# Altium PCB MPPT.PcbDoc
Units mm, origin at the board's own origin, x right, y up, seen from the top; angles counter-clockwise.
Board outline 84 x 83.24 mm, 2 copper layers (Top Layer, Bottom Layer); 69 components, 41 nets, 225 pads, 101 vias.
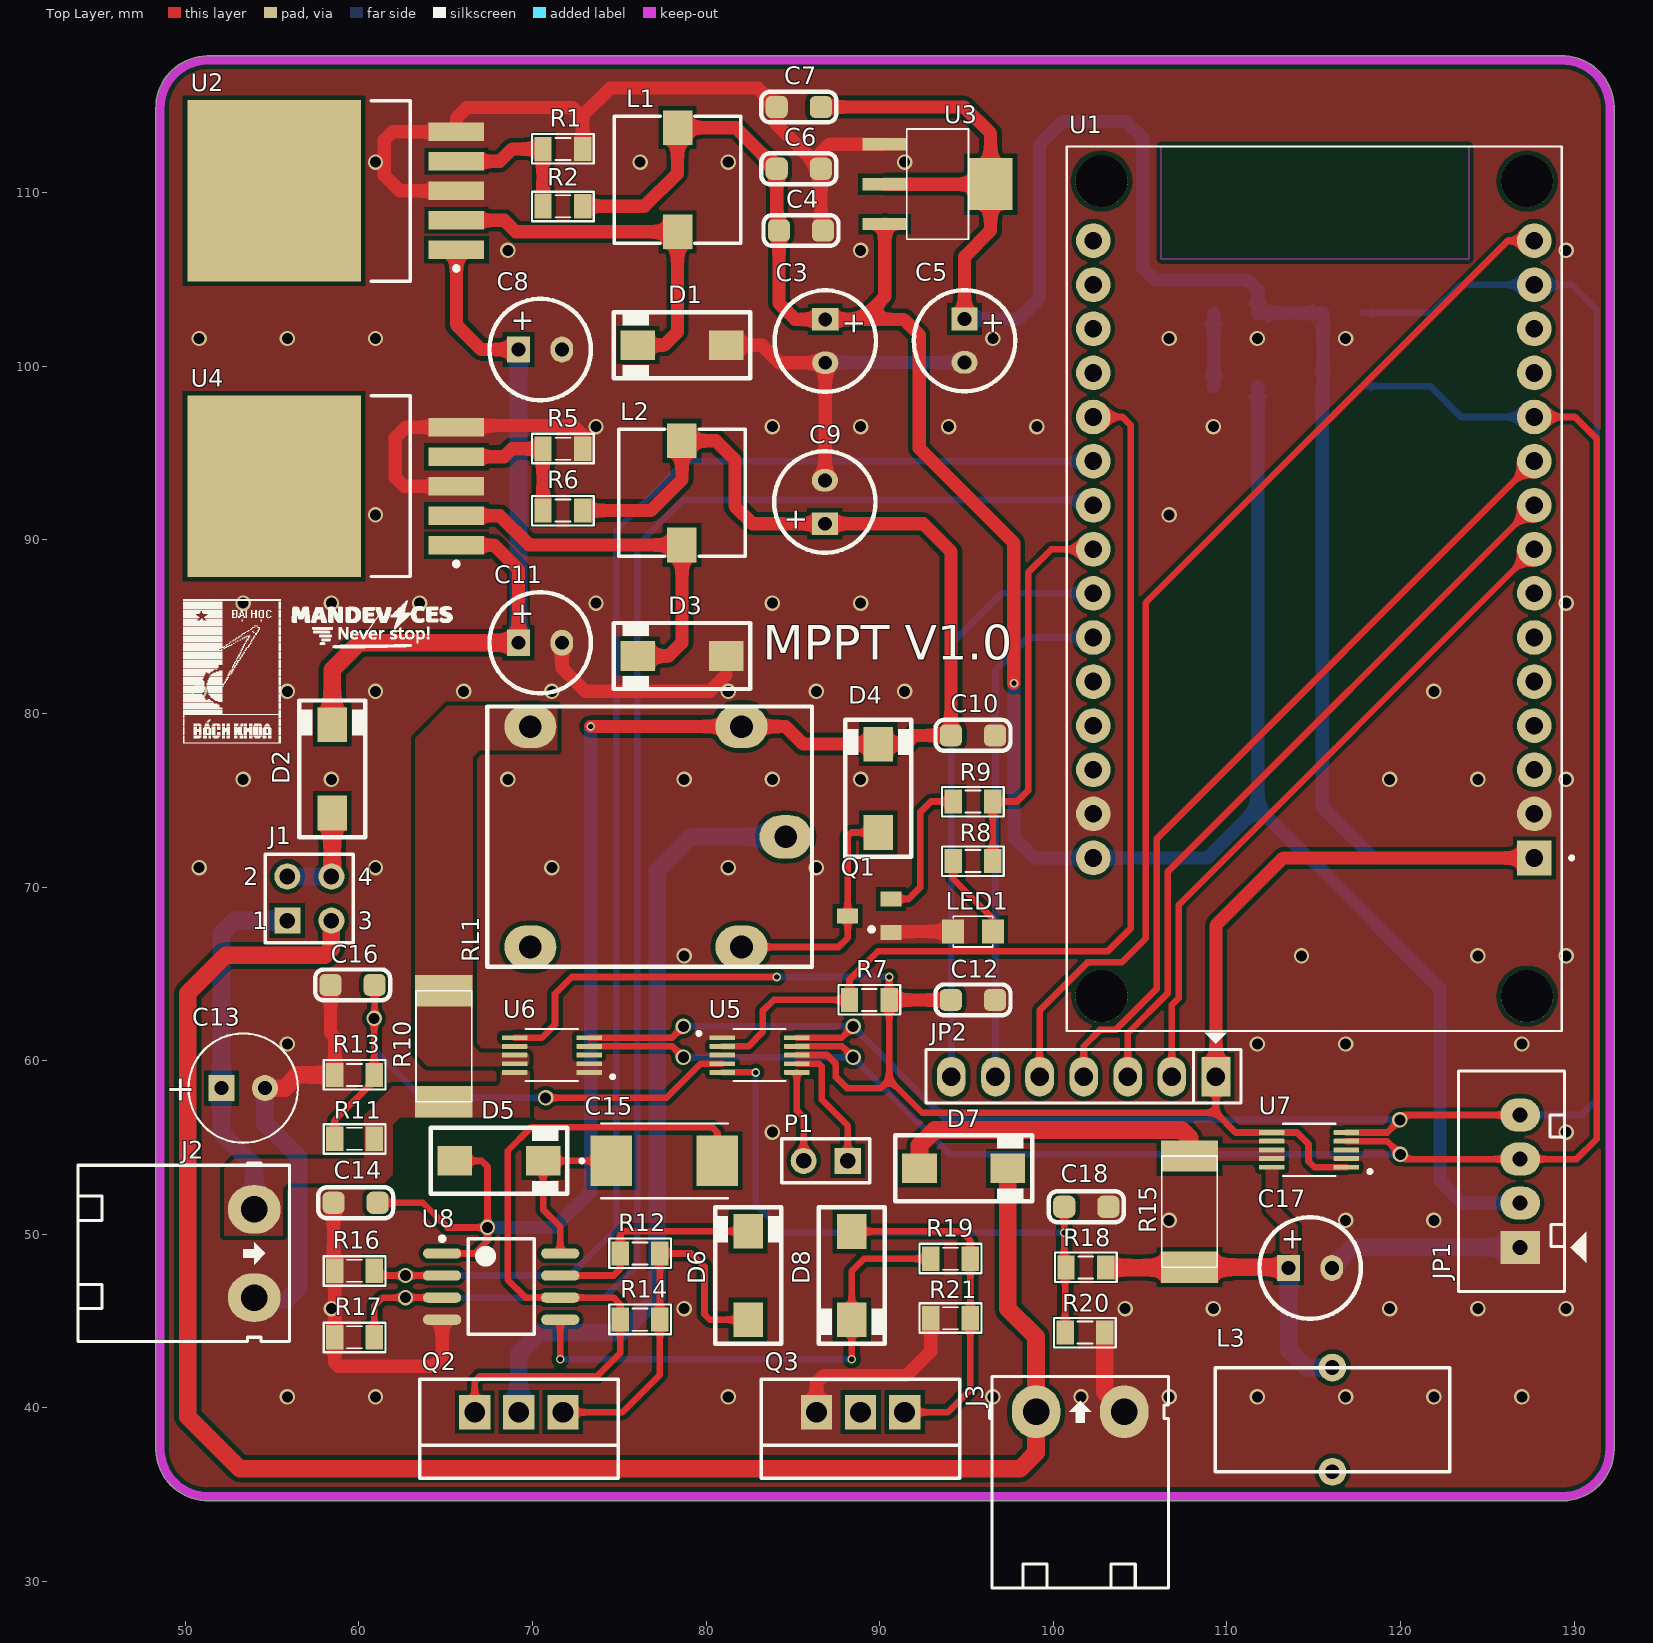
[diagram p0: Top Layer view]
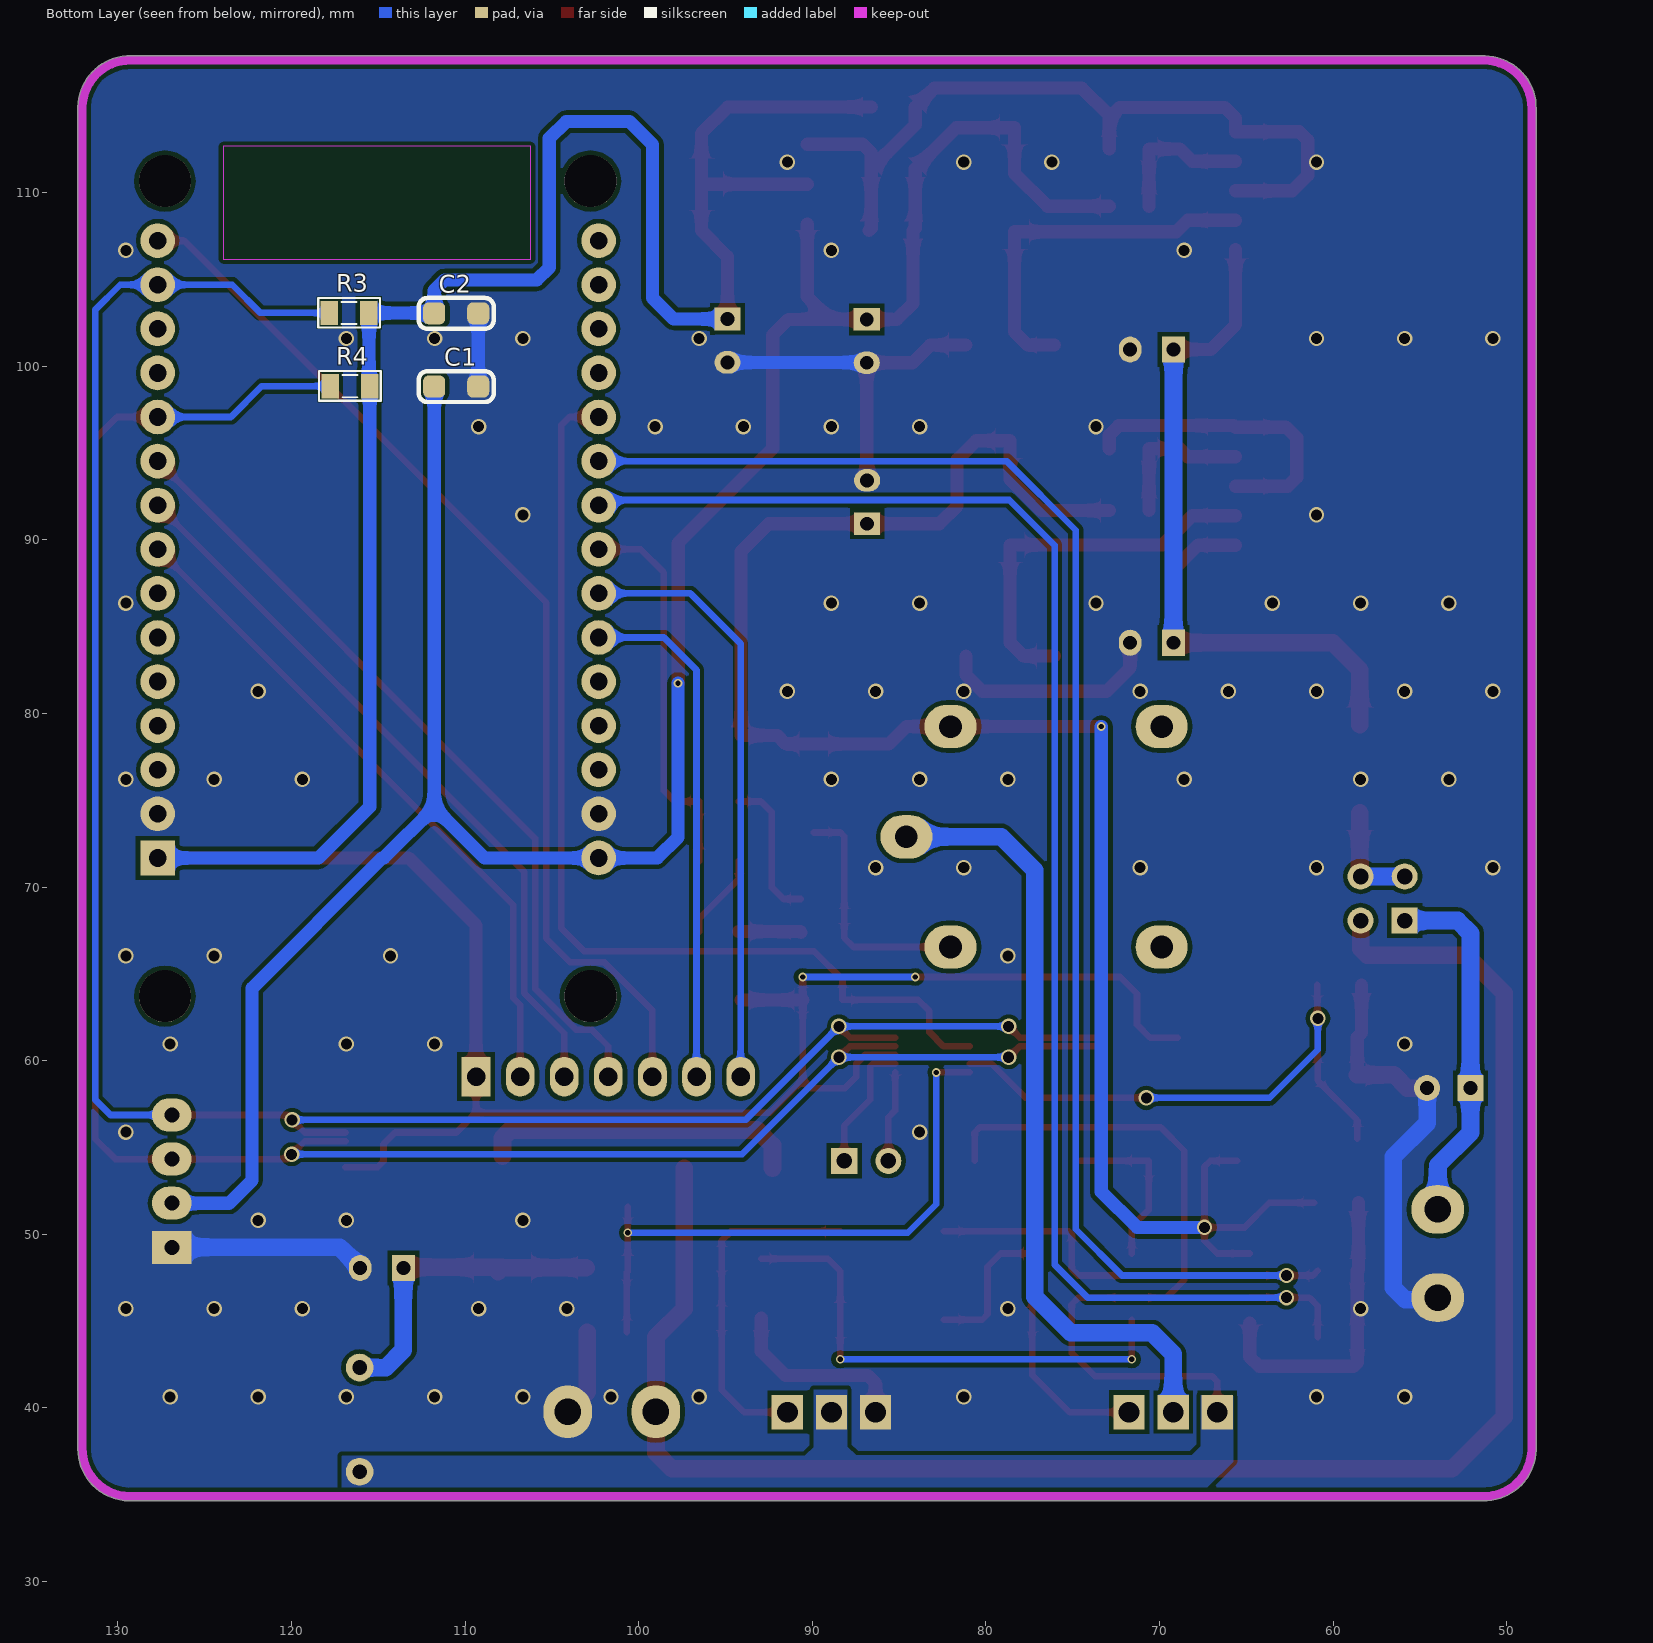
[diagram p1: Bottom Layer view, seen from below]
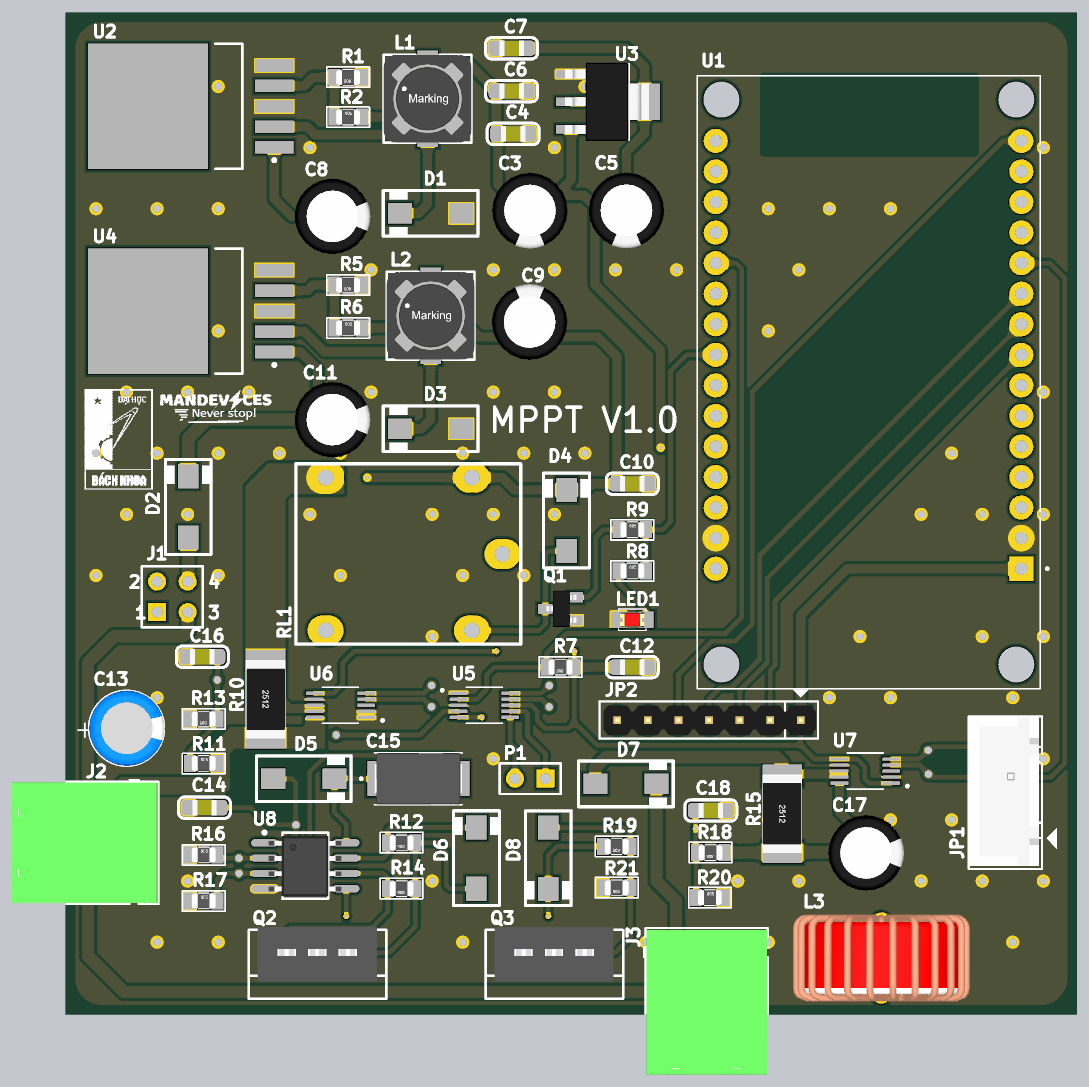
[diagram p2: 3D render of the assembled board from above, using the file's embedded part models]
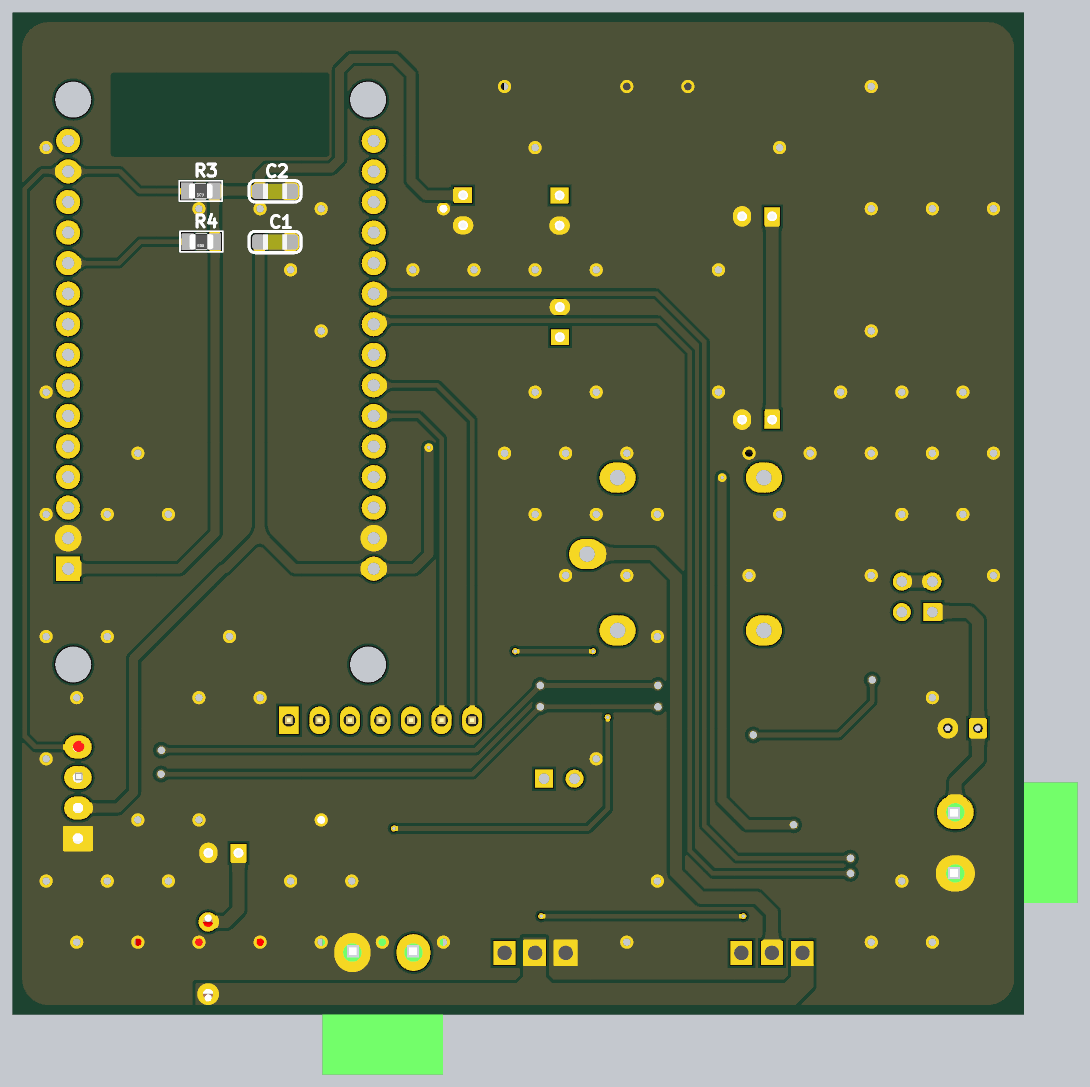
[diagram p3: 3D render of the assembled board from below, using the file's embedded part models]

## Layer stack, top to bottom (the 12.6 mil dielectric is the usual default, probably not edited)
Top Solder: solder mask 0.0102, Solder Resist, Dk 3.5
Top Layer: signal copper 0.0356
Dielectric 1: dielectric 0.32, FR-4, Dk 4.8
Bottom Layer: signal copper 0.0356
Bottom Solder: solder mask 0.0102, Solder Resist, Dk 3.5

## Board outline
48.31,37.587 cw(c48.565,37.592) 48.312,37.624 48.312,114.805 cw(c48.565,114.832) 48.311,114.828 cw(c51.308,114.884) 51.251,117.881 cw(c51.256,117.627) 51.29,117.879 cw(c51.308,117.627) 51.308,117.88 129.229,117.88 cw(c129.261,117.627) 129.256,117.882 cw(c129.312,114.885) 132.309,114.941 cw(c132.055,114.936) 132.309,114.936 cw(c132.055,114.936) 132.307,114.901 132.307,37.725 cw(c132.055,37.694) 132.309,37.698 cw(c129.312,37.642) 132.309,37.642 cw(c129.312,37.642) 129.368,34.645 cw(c129.364,34.899) 129.328,34.647 51.376,34.647 cw(c51.359,34.901) 51.364,34.647 cw(c51.308,37.644)

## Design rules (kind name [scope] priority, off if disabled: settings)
Clearance [All] p1: gap=0.254 ignorepadtopadclearanceinfootprint=TRUE
PlaneConnect [All] p1: planeconnectstyle=Direct reliefexpansion=0.508 reliefentries=4 reliefconductorwidth=0.254 reliefairgap=0.254
PolygonConnect [All] p1: connectstyle=Direct reliefconductorwidth=0.254 reliefentries=4 polygonreliefangle="90 Angle" airgapwidth=0.254
RoutingVias [All] p1: holewidth=0.305 width=0.508 viastyle="Through Hole" minholewidth=0.305 minwidth=0.508 maxholewidth=0.305 maxwidth=0.508
SolderMaskExpansion [All] p1: expansion=0.102
Width [All] p1: maxlimit=1.016 minlimit=0.381 preferedwidth=0.762
29 further rules are at their usual default settings.

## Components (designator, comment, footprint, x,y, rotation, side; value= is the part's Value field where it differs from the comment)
C1 "100nF" CAP_0805 110.515,98.831 r0 bottom value=33p
C2 "100nF" CAP_0805 110.515,103.048 r180 bottom value=33p
C3 "220uF" C8mm 86.868,101.453 r270 top
C4 "10uF" CAP_0805 85.471,107.823 r0 top value=33p
C5 "220uF" C8mm 94.889,101.473 r270 top
C6 "100nF" CAP_0805 85.344,111.379 r0 top value=33p
C7 "100nF" CAP_0805 85.344,114.935 r180 top value=33p
C8 "470uF" C8mm 70.448,100.965 r0 top
C9 "220uF" C8mm 86.843,92.182 r90 top
C10 "100nF" CAP_0805 95.377,78.74 r0 top value=33p
C11 "470uF" C8mm 70.448,84.074 r0 top
C12 "100nF" CAP_0805 95.377,63.5 r180 top value=33p
C13 "100uF/35V" CA-ALU-6.3 53.34,58.42 r0 top
C14 "100nF" CAP_0805 59.817,51.816 r180 top value=33p
C15 "10uF" CAP_35TQC10MYF 77.597,54.229 r0 top
C16 "1uF" CAP_0805 59.639,64.364 r180 top value=33p
C17 "470uF" C8mm 114.803,48.057 r0 top
C18 "1uF" CAP_0805 101.905,51.587 r0 top value=33p
D1 "1N5822" SMA 78.613,101.219 r180 top value="Diode c?m 1N5408"
D2 "SS34" SMA 58.471,76.814 r90 top
D3 "1N5822" SMA 78.613,83.312 r180 top value="Diode c?m 1N5408"
D4 "SS34" SMA 89.916,75.692 r90 top
D5 "SS34" SMA 68.076,54.229 r0 top
D6 "SS34" SMA 82.423,47.625 r90 top
D7 "SS34" SMA 94.844,53.797 r0 top
D8 "SS34" SMA 88.392,47.621 r270 top
J1 "Jumper 2x2" HDR2X2 55.88,68.072 r0 top value="JP 2x2"
J2 "KF2" KF2-5.08T 53.975,51.435 r270 top
J3 "KF2" KF2-5.08T 99.009,39.776 r0 top
JP1 "JP4" CON4 126.898,49.251 r90 top value="Connector 4"
JP2 "JP7 PIN" JP7 109.372,59.08 r180 top value=JP7
L1 "33uH" L-SMD-M-7.3x4.5 78.359,110.744 r180 top value="150 mH"
L2 "33uH" L-SMD-M-7.3x4.5 78.613,92.71 r180 top value="150 mH"
L3 "180uH" L-DIP-M-13.5x6 116.078,39.322 r90 top value="150 mH"
LED1 "LED" LED-0805-Red 96.52,67.437 r180 top value="LED 3 ly Single Colour"
P1 "Header 2" HDR1X2 88.163,54.229 r180 top
Q1 "2N222" SOT23 89.408,68.326 r90 top value=C1815
Q2 "IRF2807" TO-220 69.215,39.751 r180 top
Q3 "IRF2807" TO-220 88.9,39.751 r180 top
R1 "1k" RES-SMD-0805 71.755,112.522 r180 top
R2 "3k" RES-SMD-0805 71.755,109.22 r0 top
R3 "10k" RES-SMD-0805 116.688,103.073 r0 bottom
R4 "10k" RES-SMD-0805 116.637,98.857 r0 bottom
R5 "1.5k" RES-SMD-0805 71.755,95.25 r180 top
R6 "13k" RES-SMD-0805 71.755,91.694 r0 top
R7 "10k" RES-SMD-0805 89.408,63.5 r180 top
R8 "1k" RES-SMD-0805 95.377,71.501 r0 top
R9 "1k" RES-SMD-0805 95.377,74.93 r0 top
R10 "R050" RES-SMD-2512 64.77,60.833 r270 top
R11 "200k" RES-SMD-0805 59.753,55.499 r0 top
R12 "100R" RES-SMD-0805 76.2,48.895 r180 top
R13 "20k" RES-SMD-0805 59.753,59.182 r180 top
R14 "100k" RES-SMD-0805 76.2,45.085 r180 top
R15 "R050" RES-SMD-2512 107.721,51.308 r270 top
R16 "10k" RES-SMD-0805 59.753,47.898 r0 top
R17 "10k" RES-SMD-0805 59.753,44.069 r0 top
R18 "10k" RES-SMD-0805 101.879,48.082 r180 top
R19 "100R" RES-SMD-0805 94.082,48.59 r180 top
R20 "5.1k" RES-SMD-0805 101.829,44.348 r0 top
R21 "100k" RES-SMD-0805 94.082,45.161 r180 top
RL1 "Relay 10A/12V" RELAY5PIN-10A 84.582,72.898 r90 top value="Relay SPDT, 10A, 12V"
U1 "ESP32-DEVKIT-V1" MODULE_ESP32_DEVKIT_V1 115.011,87.194 r180 top
U2 "LM2596" TO-263 59.618,110.109 r180 top
U3 "LM1117-ADJ" LM1117-SOP 91.567,110.49 r270 top
U4 "LM2596" TO-263 59.618,93.091 r180 top
U5 "ADS1115IDGSR" SOP50P490X110-10N 83.083,60.325 r0 top
U6 "INA226AIDGSR" SOP50P490X110-10N 71.12,60.325 r180 top
U7 "INA226AIDGSR" SOP50P490X110-10N 114.741,54.864 r180 top
U8 "IR2104" SO-8N 68.199,46.99 r0 top

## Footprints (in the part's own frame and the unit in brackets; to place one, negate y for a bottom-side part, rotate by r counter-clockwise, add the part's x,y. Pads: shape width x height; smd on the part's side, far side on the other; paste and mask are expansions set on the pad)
C8mm [mm]
  rect 1.3x1.5 hole 0.8: 1(-1.25,0)
  oval 1.3x1.5 hole 0.8: 2(1.25,0)
  silkscreen extent -2.92,-2.92 2.92,2.92, body extent -3.15,-3.15 3.13,3.15, height 11.51
CA-ALU-6.3 [mm] "Polarized capacitors, Aluminum Electrolytic Capacitors, 2-Leads, Body 6.3x15x2.5x0.5"
  rect 1.5x1.5 hole 0.8: 1(-1.25,0)
  round 1.5 hole 0.8: 2(1.25,0)
  silkscreen extent -3.15,-3.15 3.15,3.15, body extent -3.12,-3.15 3.17,3.15, height 11
CAP_35TQC10MYF [mm]
  rect 2.4x2.9 smd: 1(-3.05,0) 2(3.05,0)
  silkscreen extent -4.85,-2.15 3.65,2.15, body extent -3.65,-2.15 3.65,2.15, height 1.9
CAP_0805 [mm]
  rrect50% 1.27x1.27 smd: 1(-1.27,0) 2(1.27,0)
  silkscreen extent -2.16,-0.89 2.16,0.89, body extent -1.01,-0.64 1.01,0.64, height 0.61
CON4 [mil] "CON4"
  rect 75x90 hole 34: 1(0,0)
  oval 75x90 hole 34: 2(100,0) 3(200,0) 4(300,0)
  silkscreen extent -100,-150 400,140, body extent -90,-90 398,136, height 276
HDR1X2 [mm] "Connector; Header; 2 Position"
  rect 1.5x1.5 hole 0.9: 1(0,0)
  round 1.5 hole 0.9: 2(2.54,0)
  silkscreen extent -1.27,-1.27 3.81,1.27, body extent -1.27,-1.27 3.81,1.27, height 7
HDR2X2 [mm] "Connector; Header; 2x2 Position"
  rect 1.5x1.5 hole 0.9: 1(0,0)
  round 1.5 hole 0.9: 2(0,2.54) 3(2.54,0) 4(2.54,2.54)
  silkscreen extent -1.27,-1.27 3.81,3.81, body extent -1.27,-1.27 3.81,3.81, height 7
JP7 [mil] "JP7"
  rect 65x90 hole 42: 1(0,0)
  oval 65x90 hole 42: 2(100,0) 3(200,0) 4(300,0) 5(400,0) 6(500,0) 7(600,0)
  silkscreen extent -57,-100 658,60, body extent -50,-49 646,49, height 323
KF2-5.08T [mil] "Header 2, 2 pin, hight 300mil, Pin to Pin 200, Colour Green"
  oval 110x120 hole 60: 1(0,0) 2(200,0)
  silkscreen extent -105,-400 300,80, body extent -97,-399 297,73, height 334
L-DIP-M-13.5x6 [mm] "Body 13.5x6mm, 2 leads"
  round 1.6 hole 0.85: 1(-3,0) 2(3,0)
  silkscreen extent -3,-6.75 3,6.75, body extent -3.62,-7.35 3.62,7.35, height 14.8
L-SMD-M-7.3x4.5 [mm] "WE-PDA SMD Shielded Power Inductor, 7345"
  rect 1.7x2 smd: 1(0,3) 2(0,-3)
  silkscreen extent -3.65,-3.65 3.65,3.65, body extent -3.65,-3.65 3.65,3.65, height 4.05
LED-0805-Red [mil]
  rect 50x55 smd: 1(0,0) 2(90,0)
  silkscreen extent 0,-35 90,35, body extent 5,-25 85,25, height 43
LM1117-SOP [mm]
  rect 0.7x2.54 smd: 1(-2.3,-1.27) 2(0,-1.27) 3(2.3,-1.27)
  rect 3x2.54 smd: 2(0,4.826)
  silkscreen extent -3.18,0 3.17,3.56, body extent -3.25,-1.78 3.25,5.18, height 1.68
MODULE_ESP32_DEVKIT_V1 [mm]
  rect 2x2 hole 1.02: 1(-12.7,15.515)
  round 2 hole 1.02: 2(-12.7,12.975) 3(-12.7,10.435) 4(-12.7,7.895) 5(-12.7,5.355) 6(-12.7,2.815) 7(-12.7,0.275) 8(-12.7,-2.265) 9(-12.7,-4.805) 10(-12.7,-7.345) 11(-12.7,-9.885) 12(-12.7,-12.425) 13(-12.7,-14.965) 14(-12.7,-17.505) 15(-12.7,-20.045) 16(12.7,-20.045) 17(12.7,-17.505) 18(12.7,-14.965) 19(12.7,-12.425) 20(12.7,-9.885) 21(12.7,-7.345) 22(12.7,-4.805) 23(12.7,-2.265) 24(12.7,0.275) 25(12.7,2.815) 26(12.7,5.355) 27(12.7,7.895) 28(12.7,10.435) 29(12.7,12.975) 30(12.7,15.515)
  round 3 hole 3 unplated: ""(-12.28,23.475) ""(-12.28,-23.475) ""(12.23,23.475) ""(12.23,-23.475)
  Keep-Out Layer region: 8.78,-25.475 -8.91,-25.475 -8.91,-18.985 8.78,-18.985
  Keep-Out Layer region: 8.78,-25.475 -8.91,-25.475 -8.91,-18.985 8.78,-18.985
  silkscreen extent -14.95,-25.48 14.23,25.48
RELAY5PIN-10A [mm]
  oval 2.5x3 hole 1.3: 1(0,0) 2(-6.35,14.7) 3(6.35,14.7) 4(-6.35,2.54) 5(6.35,2.54)
  silkscreen extent -7.49,-1.52 7.51,17.18, body extent -7.49,-1.52 7.49,17.14, height 16
RES-SMD-0805 [mil]
  rect 39.37x55 smd: 1(-45,0) 2(45,0)
  silkscreen extent -70,-34 70,33, body extent -39,-25 39,25, height 31
RES-SMD-2512 [mm] "Chip Capacitor, Body 3.2x2.5mm, IPC Medium Density"
  rect 1.8x3.3 smd: 1(-3.2,0.127) 2(3.2,0.127)
  silkscreen extent -3.2,-1.47 3.2,1.73, body extent -3.2,-1.47 3.2,1.73, height 0.6
SMA [mm]
  rect 2x1.7 smd: 1(-2.544,0) 2(2.544,0)
  silkscreen extent -3.94,-1.9 3.94,1.91, body extent -2.87,-1.4 2.87,1.4, height 2.29
SO-8N [mm] "SOP, 8-Leads, Body 5.3x5.3mm, Pitch 1.27mm, IPC Medium Density"
  oval 2.2x0.6 smd: 1(-3.4,1.905) 2(-3.4,0.635) 3(-3.4,-0.635) 4(-3.4,-1.905) 5(3.4,-1.905) 6(3.4,-0.635) 7(3.4,0.635) 8(3.4,1.905)
  silkscreen extent -3.52,-2.75 1.9,2.88, body extent -3.05,-2.54 3,2.48, height 1.6
SOP50P490X110-10N [mm]
  rrect25% 1.47x0.28 smd: 1(-2.15,1) 2(-2.15,0.5) 3(-2.15,0) 4(-2.15,-0.5) 5(-2.15,-1) 6(2.15,-1) 7(2.15,-0.5) 8(2.15,0) 9(2.15,0.5) 10(2.15,1)
  silkscreen extent -3.6,-1.5 1.5,1.5
SOT23 [mm] "SOT 23 _ 1-3-2"
  rect 0.85x1.2 smd: 1(-0.94,-1.245) 2(0.985,-1.25) 3(0.005,1.25)
  silkscreen extent -0.88,-0.25 -0.64,0, body extent -1.47,-1.33 1.53,1.17, height 1.06
TO-220 [mm]
  rect 1.8x2 hole 1.2: 1(-2.54,0) 2(0,0) 3(2.54,0)
  silkscreen extent -5.72,-1.91 5.71,3.81, body extent -4.92,-2.13 4.98,2.37, height 8.08
TO-263 [mm]
  rect 3.2x1.05 smd: 1(-6,3.4) 2(-6,1.7) 3(-6,0) 4(-6,-1.7) 5(-6,-3.4)
  rect 10x10.45 smd: 6(4.5,0)
  silkscreen extent -6.13,-5.2 -1.1,5.2, body extent -6.58,-5.2 7.57,5.2, height 4.65

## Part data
C1 C2 C4 C6 C7 C10 C12 C14 C16 C18: library part CapSMD, "Capacitor"
C3 C5 C9 C15: library part "Cap Pol", "220uF 25V 6x7mm"
C8 C11: library part "Cap Pol", "220uF 50V 8x12mm"
C13: library part "Cap Pol", "Polarized Capacitor (Axial)"
C17: library part "Cap Pol", "470uF 50V 8x12mm"
D1 D3: "Schottky Rectifiers"
D2 D6 D7 D8: library part "Diode SS34 ( 1N5822 )", "Dán"
D4 D5: library part "Diode SS34 ( 1N5822 )"
J1: library part JP2x2
J2 J3: Manufacturer="Würth Elektronik eiSos GmbH", partNo=691103110002
JP1: library part Con4, "Connector 4"
JP2: library part JP7
L1 L2: library part "Inductor Ferit", "33uH CD127 3A 12x12x7mm"
L3: library part Inductor, "180uH 4A 13mm"
LED1: "LED Single colour Green and Red"
P1: "Header, 2-Pin"
Q1: "NPN 600mW, ECB"
R1 R2 R3 R4 R5 R6 R7 R8 R9 R11 R12 R13 R14 R16 R17 R18 R19 R20 R21: library part "Resistor - SMD", "Resistor", Manufacturer="Generic Components"
R10 R15: library part "Resistor - SMD", "Resistor SMD", Manufacturer="Generic Components"
RL1: library part "Relay 5", "Relay SPDT,10A - 12VDC 5 Pin"
U1: "Dual core, Wi-Fi: 2.4 GHz up to 150 Mbits/s,BLE (Bluetooth Low Energy) and legacy Bluetooth, 32 bits, Up to 240 MHz", Package=None
U2 U4: Max Input Voltage="12 V", Max Output Current="3 (6.0 peak) A", Max Output Voltage=mV, Temperature Range="-40 to +125 degC"
U3: "800mA Low-Dropout Linear Regulator"
U5: Package=None
U6 U7: "36V, 16-bit, ultra-precise i2c output current/voltage/power monitor w/alert 10-VSSOP -40 to 125", Package="VSSOP-10 Texas Instruments"
U8: library part IR2184, "Half-Bridge Driver"

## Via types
v1: diameter 0.889, hole 0.635, Top Layer to Bottom Layer, 82 vias
v2: diameter 0.889, hole 0.635, Top Layer to Bottom Layer, tented both sides, 11 vias
v3: diameter 0.508, hole 0.305, Top Layer to Bottom Layer, 8 vias

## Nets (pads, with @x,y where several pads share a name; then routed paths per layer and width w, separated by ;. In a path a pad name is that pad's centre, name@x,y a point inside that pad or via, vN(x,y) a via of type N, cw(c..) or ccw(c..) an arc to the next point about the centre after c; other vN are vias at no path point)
3V3: C2.1 C5.1 C7.1 C12.2 JP2.1 R3.1 R4.1 R7.1 U1.1 U3.2 U5.8 U6.6 U7.1 U7.6 | length 210
  Top Layer w0.381: U6.6 70.545,61.325 71.298,62.078 71.298,63.856 72.263,64.821 v3(84.074,64.821) ; U5.8 86.97,60.325 87.478,59.817 87.478,59.055 88.113,58.42 90.068,58.42 90.551,58.903 ; v3(90.551,64.821) R7.1 90.551,58.903 ; JP2.1 109.372,56.998 ; U7.1 115.046,53.864 114.706,54.204 114.706,55.194 114.037,55.864 U7.6 110.506,55.864 109.372,56.998 ; 90.551,58.903 92.456,56.998 109.372,56.998
  Top Layer w0.762: C7.1 94.869,114.935 96.393,113.411 U3.2@96.393,110.49 ; U3.2@90.297,110.49 U3.2@96.393,110.49 ; R7.1 C12.2 ; C5.1 94.889,106.319 96.393,107.823 U3.2@96.393,110.49 ; JP2.1 109.372,67.793 113.259,71.679 U1.1
  Bottom Layer w0.381: v3(84.074,64.821) v3(90.551,64.821)
  Bottom Layer w0.762: C5.1 97.999,102.723 99.212,103.937 99.212,112.776 100.533,114.097 104.191,114.097 105.156,113.132 105.156,105.689 105.867,104.978 111.176,104.978 111.785,104.369 C2.1 111.811,103.073 R3.1 115.545,98.908 R4.1 115.494,74.625 118.44,71.679 U1.1
+5: C1.2 C3.1 C4.1 C6.1 JP1.2 L1.2 R2.2 U1.30 U3.3 | length 140.4
  Top Layer w0.762: R2.2 76.454,109.22 78.359,111.125 L1.2 81.709,113.744 C6.1 84.074,107.95 C4.1 84.201,103.632 85.13,102.703 C3.1 88.987,102.703 ; U3.3 90.297,104.013 88.987,102.703 ; v3@97.727,81.737 97.727,89.827 92.278,95.275 92.278,101.803 91.378,102.703 88.987,102.703
  Bottom Layer w0.762: v3(97.739,81.737) 97.739,72.873 98.933,71.679 U1.30 108.89,71.679 111.785,74.574 ; C1.2 111.785,74.574 ; JP1.2 123.596,51.791 122.276,53.111 122.276,64.184 114.781,71.679 114.681,71.679 111.785,74.574
+12: C9.1 C10.1 C14.1 D4.2 D5.1 L2.2 R6.2 RL1.5 U8.1 | length 110.1
  Top Layer w0.381: C14.1 63.678,51.816 65.1,50.394 v2(67.412,50.394) ; U8.1 66.675,48.895 67.412,49.632 v2(67.412,50.394) ; D5.1 67.081,54.229 67.412,53.899 v2(67.412,50.394)
  Top Layer w0.762: R6.2 76.835,91.694 78.613,93.472 L2.2 80.566,95.71 81.661,94.615 81.661,91.948 82.677,90.932 C9.1 92.507,90.932 94.107,89.332 C10.1 92.024,78.74 91.52,78.236 D4.2 85.594,78.236 84.582,79.248 RL1.5 v3(73.355,79.248)
  Bottom Layer w0.762: v2(67.412,50.394) 71.298,50.394 73.355,52.451 v3(73.355,79.248)
ADC_SCL: JP1.4 R3.2 U1.14 U5.10 U6.5 U7.5 | length 128.2
  Top Layer w0.381: U6.5 78.038,61.325 v2(78.689,61.976) ; U5.10 87.817,61.325 v2(88.468,61.976) ; U7.5 119.237,55.864 v2(119.964,56.591) 120.244,56.871 JP1.4
  Bottom Layer w0.381: v2(78.689,61.976) v2(88.468,61.976) 93.853,56.591 94.031,56.591 v2(119.964,56.591) ; R3.2 121.793,103.073 123.419,104.699 U1.14 129.87,104.699 131.318,103.251 131.318,57.76 130.429,56.871 JP1.4
ADC_SDA: JP1.3 R4.2 U1.11 U5.9 U6.4 U7.4 | length 123.8
  Top Layer w0.381: U6.4 78.062,60.825 v2(78.689,60.198) ; U5.9 87.841,60.825 v2(88.468,60.198) ; U7.4 119.236,55.364 v2(119.99,54.61) 120.269,54.331 JP1.3 130.15,54.331 131.318,55.499 131.318,95.809 130.048,97.079 U1.11
  Bottom Layer w0.381: v2(78.689,60.198) v2(88.468,60.198) 94.056,54.61 94.183,54.61 v2(119.99,54.61) ; R4.2 121.717,98.857 123.495,97.079 U1.11 ; JP1.3@126.619,54.61 JP1.3 ; JP1.3@126.784,54.216 JP1.3@126.898,54.102
BAT+: D7.2 J1.3 J3.1 | length 102.9
  Top Layer w1.016: J1.3 58.42,66.446 58.039,66.065 52.324,66.065 50.14,63.881 50.14,39.497 53.137,36.5 98.095,36.5 99.009,37.414 J3.1 99.009,44.094 97.388,45.716 D7.2
ESP32_GPIO25: R8.2 R9.2 U1.23 | length 22.6
  Top Layer w0.381: R8.2 R9.2 97.917,74.93 98.552,75.565 98.552,88.113 99.898,89.459 U1.23
ESP32_GPIO26: JP2.7 U1.24 | length 34.3
  Bottom Layer w0.381: JP2.7 94.132,84.023 97.028,86.919 U1.24
ESP32_GPIO27: JP2.6 U1.25 | length 29.8
  Bottom Layer w0.381: JP2.6 96.672,82.499 98.552,84.379 U1.25
ESP32_GPIO32: R16.2 U1.21 U8.2 | length 86.7
  Top Layer w0.381: R16.2 61.17,47.625 v2(62.687,47.625) U8.2
  Bottom Layer w0.381: v2(62.687,47.625) 72.161,47.625 74.828,50.292 74.828,90.551 78.816,94.539 U1.21
ESP32_GPIO33: R17.2 U1.22 U8.3 | length 89
  Top Layer w0.381: R17.2 60.896,45.885 61.366,46.355 v2(62.687,46.355) U8.3
  Bottom Layer w0.381: v2(62.687,46.355) 74.143,46.355 76.048,48.26 76.048,89.687 78.661,92.301 102.009,92.301 U1.22
ESP32_GPIO35: R7.2 U1.20 U5.2 | length 59.1
  Top Layer w0.381: U5.2 82.44,60.825 83.261,61.646 83.261,62.865 83.896,63.5 R7.2 88.265,64.668 89.895,66.298 93.411,66.298 93.415,66.294 95.053,66.294 95.057,66.298 95.697,66.298 95.701,66.294 97.339,66.294 97.343,66.298 103.128,66.298 104.47,67.64 104.47,96.596 103.988,97.079 U1.20
ESP32_MISO: JP2.4 U1.10 | length 46.7
  Top Layer w0.381: JP2.4 101.752,60.835 102.692,61.774 103.587,61.774 105.969,64.156 105.969,72.796 U1.10
ESP32_MOSI: JP2.5 U1.15 | length 62
  Top Layer w0.381: JP2.5 99.212,62.9 101.976,65.663 103.95,65.663 105.334,67.047 105.334,86.385 126.187,107.239 U1.15
ESP32_SCK: JP2.3 U1.9 | length 42.6
  Top Layer w0.381: JP2.3 104.292,61.582 106.604,63.893 106.604,70.891 U1.9
ESP32_SS: JP2.2 U1.8 | length 39
  Top Layer w0.381: JP2.2 106.832,63.224 107.239,63.63 107.239,68.986 U1.8
GND: C1.1 C2.2 C3.2 C4.2 C5.2 C6.2 C7.2 C8.2 C9.2 C10.2 C11.2 C12.1 C13.2 C14.2 C16.2 C17.2 C18.2 D1.1 D3.1 J2.2 J3.2 JP1.1 LED1.2 Q1.1 Q3.3 R1.1 R5.1 R13.2 R16.1 R17.1 R20.2 R21.2 U1.2 U1.29 U2.3 U2.5 U3.1 U4.3 U4.5 U5.1 U5.3 U6.1 U6.2 U6.7 U7.2 U7.7 U8.4 | length 176.3
  Top Layer w0.762: C16.2 58.369,61.595 58.611,61.354 R13.2 ; C14.2 58.547,47.962 R16.1 R17.1 58.61,42.609 58.826,42.393 64.262,42.393 64.799,42.93 U8.4@64.799,44.882 ; U4.3 62.611,93.091 62.103,93.599 62.103,95.885 62.709,96.491 U4.5 65.711,96.584 72.352,96.584 72.898,96.037 R5.1 ; U2.3 62.357,110.109 61.468,110.998 61.468,113.03 61.947,113.509 U2.5 65.618,114.284 66.243,114.91 72.288,114.91 72.898,114.3 ; C11.2 71.698,82.632 73.05,81.28 80.213,81.28 81.157,82.224 D3.1 ; R1.1 72.898,114.3 ; D1.1 83.21,101.219 84.226,100.203 C3.2 86.868,93.457 C9.2 ; Q3.3 86.36,41.427 86.792,41.859 91.542,41.859 92.939,43.256 R21.2 ; C4.2 86.614,107.95 C6.2 ; U3.1 87.111,112.79 86.614,112.293 C6.2 ; Q1.1 90.703,67.437 LED1.2 ; 72.898,114.3 72.898,114.452 74.473,116.027 82.982,116.027 C7.2 84.074,113.919 C6.2
  Top Layer w1.016: C13.2 55.728,58.42 56.49,59.182 R13.2 ; R20.2 102.972,40.894 J3.2
  Bottom Layer w0.762: C3.2 86.888,100.223 C5.2 ; C1.1 C2.2
  Bottom Layer w1.016: J2.2 54.102,46.228 55.855,46.228 56.54,46.914 56.54,54.458 54.59,56.408 C13.2 ; C17.2 116.053,48.082 117.221,49.251 JP1.1
  other v1: 55.88,40.64 60.96,40.64 81.28,40.64 96.52,40.64 101.6,40.64 106.68,40.64 111.76,40.64 116.84,40.64 121.92,40.64 127,40.64 58.42,45.72 78.74,45.72 104.14,45.72 109.22,45.72 119.38,45.72 124.46,45.72 129.54,45.72 106.68,50.8 116.84,50.8 121.92,50.8 83.82,55.88 129.54,55.88 55.88,60.96 111.76,60.96 116.84,60.96 127,60.96 78.74,66.04 114.3,66.04 124.46,66.04 129.54,66.04 50.8,71.12 60.96,71.12 71.12,71.12 81.28,71.12 86.36,71.12 53.34,76.2 58.42,76.2 68.58,76.2 78.74,76.2 83.82,76.2 88.9,76.2 119.38,76.2 124.46,76.2 129.54,76.2 50.8,81.28 55.88,81.28 60.96,81.28 66.04,81.28 71.12,81.28 81.28,81.28 86.36,81.28 91.44,81.28 121.92,81.28 53.34,86.36 58.42,86.36 63.5,86.36 73.66,86.36 83.82,86.36 88.9,86.36 129.54,86.36 60.96,91.44 106.68,91.44 73.66,96.52 83.82,96.52 88.9,96.52 93.98,96.52 99.06,96.52 109.22,96.52 50.8,101.6 55.88,101.6 60.96,101.6 96.52,101.6 106.68,101.6 111.76,101.6 116.84,101.6 68.58,106.68 88.9,106.68 129.54,106.68 60.96,111.76 76.2,111.76 81.28,111.76 91.44,111.76
NetC8_1: C8.1 C11.1 D2.2 U2.1 U4.1 | length 48.3
  Top Layer w0.762: U4.1 67.789,89.691 69.198,88.282 C11.1 ; U2.1 65.618,102.403 67.056,100.965 C8.1
  Top Layer w1.016: D2.2 58.471,82.525 60.02,84.074 C11.1
  Bottom Layer w1.016: C11.1 C8.1
NetC15_1: C15.1 D5.2 U8.8 | length 9.7
  Top Layer w0.381: U8.8 71.599,50.448 70.616,51.431 70.616,54.229 C15.1
NetC15_2: C15.2 L3.1 Q2.3 Q3.2 R14.2 U8.6 | length 42.5
  Top Layer w0.381: Q2.3 66.675,41.529 66.98,41.834 73.736,41.834 75.057,43.155 R14.2 75.057,45.974 74.676,46.355 U8.6 69.596,46.355 68.58,47.371 68.58,54.813 69.926,56.159 80.366,56.159 80.647,55.878 C15.2
NetC17_1: C17.1 L3.2 R15.2 R18.1 U7.10 | length 18.6
  Top Layer w1.016: R18.1 107.874,48.082 R15.2@108.103,47.854 ; R15.2 113.502,48.108 C17.1
  Bottom Layer w1.016: C17.1@113.563,48.057 113.563,43.332 114.574,42.322 L3.2
NetD1_2: D1.2 L1.1 U2.2 | length 21.4
  Top Layer w0.762: U2.2 68.375,108.409 69.04,107.744 L1.1 78.359,101.981 77.597,101.219 D1.2
NetD2_1: D2.1 J1.2 J1.4 | length 6.2
  Top Layer w1.016: J1.4 58.471,70.663 D2.1
  Bottom Layer w1.016: J1.2 J1.4
NetD3_2: D3.2 L2.1 U4.2 | length 22.2
  Top Layer w0.762: U4.2 68.121,91.391 69.802,89.71 L2.1 78.613,84.074 77.851,83.312 D3.2
NetD4_1: D4.1 Q1.3 RL1.4 | length 14
  Top Layer w0.381: RL1.4 87.63,66.548 88.158,67.076 Q1.3 88.158,72.918 88.388,73.148 D4.1
NetD6_1: D6.1 Q2.1 R12.1 R14.1 | length 21.7
  Top Layer w0.381: Q2.1 75.184,39.751 77.343,41.91 R14.1 R12.1 79.146,48.895 79.908,48.133 79.908,45.39 80.217,45.081 D6.1
NetD6_2: D6.2 R12.2 U8.7 | length 13
  Top Layer w0.381: U8.7 74.676,47.625 75.057,48.006 R12.2 75.057,49.987 75.239,50.169 D6.2
NetD8_1: D8.1 Q3.1 R19.1 R21.1 | length 20
  Top Layer w0.381: D8.1 94.691,50.165 95.225,49.632 R19.1 R21.1 95.225,41.046 93.929,39.751 Q3.1
NetD8_2: D8.2 R19.2 U8.5 | length 29
  Top Layer w0.381: v3(71.599,42.803) U8.5 ; v3(88.392,42.799) D8.2 88.392,47.879 89.103,48.59 R19.2
  Bottom Layer w0.381: v3(71.599,42.803) 71.603,42.799 v3(88.392,42.799)
NetLED1_1: LED1.1 R8.1 | length 5
  Top Layer w0.381: R8.1 94.234,70.485 96.52,68.199 LED1.1
NetP1_1: P1.1 U5.7 | length 7.6
  Top Layer w0.381: U5.7 86.504,59.825 86.665,59.665 86.665,57.76 88.163,56.261 P1.1
NetP1_2: P1.2 U5.6 | length 5.3
  Top Layer w0.381: U5.6 85.233,57.134 85.623,56.744 P1.2
NetQ1_2: Q1.2 R9.1 | length 8.4
  Top Layer w0.381: Q1.2 91.663,69.311 92.329,69.977 92.329,74.295 92.964,74.93 R9.1
NetQ2_2: Q2.2 RL1.1 | length 45.4
  Bottom Layer w1.016: Q2.2 69.215,43.104 70.434,44.323 75.108,44.323 77.191,46.406 77.191,70.968 79.121,72.898 RL1.1
NetR1_2: R1.2 R2.1 U2.4 | length 8.6
  Top Layer w0.762: U2.4 68.121,111.809 68.834,112.522 R1.2 R2.1
NetR5_2: R5.2 R6.1 U4.4 | length 8.7
  Top Layer w0.762: U4.4 68.375,94.791 68.834,95.25 R5.2 R6.1
SOLAR+: C13.1 J1.1 J2.1 R10.2 R11.2 U6.10 | length 20.8
  Bottom Layer w1.016: J2.1 53.975,53.975 52.09,55.86 C13.1 52.09,67.33 52.832,68.072 J1.1
VADC_BAT: C18.1 R18.2 R20.1 U5.5 | length 35.2
  Top Layer w0.381: U5.5 v3(82.864,59.325) ; C18.1 v3(100.635,50.089) 100.635,47.854 100.686,47.803 R20.1
  Bottom Layer w0.381: v3(82.864,59.325) 82.864,51.73 84.506,50.089 v3(100.635,50.089)
VADC_SOL: C16.1 R11.1 R13.1 U5.4 | length 33.6
  Top Layer w0.381: R11.1 58.61,56.578 60.897,58.865 R13.1 60.884,59.195 v2(60.884,62.433) 60.909,62.459 C16.1 ; v2(70.764,57.861) 77.724,57.861 79.688,59.825 U5.4
  Bottom Layer w0.381: v2(60.884,62.433) 60.884,60.63 63.652,57.861 v2(70.764,57.861)
VBUS_BAT: D7.1 R15.1 U7.8 U7.9 | length 18.5
  Top Layer w1.016: D7.1 92.3,55.139 93.167,56.007 107.391,56.007 107.848,55.55 R15.1
VBUS_SOL: R10.1 RL1.3 U6.8 U6.9
pads on no net: RL1.2 U1. U1.3 U1.4 U1.5 U1.6 U1.7 U1.12 U1.13 U1.16 U1.17 U1.18 U1.19 U1.26 U1.27 U1.28 U2.6 U4.6 U6.3 U7.3

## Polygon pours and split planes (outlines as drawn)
GND on Top Layer (solid, remove dead copper, pour order 112): 45.923,119.278 44.475,117.831 44.475,26.721 136.728,26.721 139.624,29.616 138.481,30.759 138.481,128.27
VBUS_BAT on Top Layer "Top Layer-BAT+" (solid, pour order 106): 113.309,54.991 107.061,54.991 107.061,54.229 107.137,54.229 113.309,54.229
NetC17_1 on Top Layer "Top Layer-NetC17_1" (solid, pour order 104): 112.243,54 112.954,54 112.954,51.613 114.071,50.495 114.071,47.32 113.055,47.32 113.055,50.495 112.243,51.308
no net on Top Layer "Top Layer-No Net 4" (solid, pour order 102): 112.116,54
no net on Top Layer "Top Layer-No Net 5" (solid, pour order 98): 113.309,54.991
no net on Top Layer "Top Layer-No Net 6" (solid, pour order 90): 118.288,39.472
no net on Top Layer "Top Layer-No Net 7" (solid, pour order 84): 102.184,44.45
VBUS_SOL on Top Layer "Top Layer-VBUS_SOL" (solid, pour order 62): 69.825,60.452 66.98,60.452 66.548,60.884 66.548,65.024 63.246,65.024 63.246,60.418 63.933,59.69 69.825,59.69
VBUS_SOL on Top Layer "Top Layer-VBUS_SOL 1" (solid, pour order 70): 66.548,63.043 66.548,77.47 66.954,77.876 71.425,77.876 71.425,80.442 65.1,80.442 63.246,78.588 63.246,63.043
no net on Top Layer "Top Layer-No Net 8" (solid, pour order 42): 114.351,54.432
SOLAR+ on Top Layer "Top Layer-SOLAR+" (solid, pour order 38): 52.248,49.911 55.626,49.911 55.626,52.654 55.905,52.934 61.468,52.934 61.951,53.416 61.951,54.356 60.3,54.356 52.832,54.356 52.248,53.772
SOLAR+ on Top Layer "Top Layer-SOLAR+ 1" (solid, pour order 34): 63.094,58.522 61.951,58.522 60.3,56.871 60.3,54.356 61.951,54.356 61.951,56.312 62.382,56.744 63.094,56.744
no net on Top Layer "Top Layer-No Net 9" (solid, pour order 32): 60.401,56.185
SOLAR+ on Top Layer "Top Layer-SOLAR+ 2" (solid, pour order 30): 63.094,58.522 67.945,58.522 68.174,58.75 68.174,59.512 69.85,59.512 69.85,56.744 63.094,56.744
no net on Top Layer "Top Layer-No Net 10" (solid, pour order 28): 63.094,58.522
no net on Top Layer "Top Layer-No Net" (solid, pour order 14): 62.713,58.547
no net on Top Layer "Top Layer-No Net 1" (solid, pour order 10): 64.897,57.633
no net on Top Layer "Top Layer-No Net 2" (solid, pour order 6): 114.351,54.432
no net on Top Layer "Top Layer-No Net 3" (solid, pour order 4): 114.351,54.432
GND on Bottom Layer (solid, remove dead copper, pour order 114): 44.475,32.029 139.903,32.029 147.752,39.878 138.76,48.87 138.76,122.352 32.309,122.352 31.521,123.139
NetC15_2 on Bottom Layer "Bottom Layer-NetC15_2" (solid, pour order 96): 102.514,37.236 117.094,37.236 117.119,37.211 117.119,35.408 103.708,35.408 102.514,35.408
no net on Bottom Layer "Bottom Layer-No Net" (solid, pour order 94): 103.683,37.236
NetC15_2 on Bottom Layer "Bottom Layer-NetC15_2 1" (solid, pour order 78): 88.181,35.408 103.708,35.408 103.708,37.262 103.683,37.236 90.424,37.236 89.788,37.872
no net on Bottom Layer "Bottom Layer-No Net 1" (solid, pour order 72): 88.392,35.408
NetC15_2 on Bottom Layer "Bottom Layer-NetC15_2 2" (solid, pour order 52): 65.761,40.753 65.761,36.906 67.259,35.408 88.392,35.408 89.916,36.932 89.916,41.046 87.986,41.046 87.986,37.77 87.478,37.262 68.148,37.262 67.615,37.795 67.615,40.728

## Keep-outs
Keep-Out Layer:
  lines w0.504: 48.565,37.592 48.565,114.884 ; 51.308,117.627 129.261,117.627 ; 51.359,34.9 129.364,34.9 ; 132.055,37.694 132.055,114.936
  lines w0.508: 48.565,37.592 ccw(c51.308,37.644) 51.359,34.901 ; 48.565,114.832 cw(c51.308,114.884) 51.256,117.627 ; 129.261,117.627 cw(c129.312,114.885) 132.055,114.936 ; 129.364,34.899 ccw(c129.312,37.642) 132.055,37.694

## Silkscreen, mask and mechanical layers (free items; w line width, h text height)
Top Overlay:
  drawing of 1604 lines, arcs and shapes, not listed
  text "MPPT V1.0" at 83.261,83.083 h2

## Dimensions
51.359,34.9 to 51.308,117.627 on Mechanical 15
48.565,114.884 to 132.055,114.936 on Mechanical 15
